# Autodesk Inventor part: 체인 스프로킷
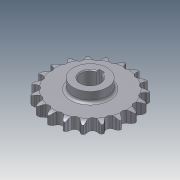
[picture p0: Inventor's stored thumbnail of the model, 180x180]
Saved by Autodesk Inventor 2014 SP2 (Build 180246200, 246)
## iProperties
Created: 2013-01
Part Number: 체인 스프로킷
Material: 강
Document SubType Name: Modeling
Designer: KYOUNG IL JANG
Density: 1 g/cm^3
Appearance: 강철
CustomPartVersion: 1
Company: 한국ATC센터
Author: KYOUNG IL JANG
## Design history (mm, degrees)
sketch "이론적 톱니 프로파일"
  geometry: L1 (0, 0)-(0, 45.567); L2 (0, 0)-(14.795, 43.098); L3 (0, 45.567)-(14.795, 43.098); L4 (0, 45.567)-(5.661, 50.015); L5 (5.661, 50.015)-(-5.141, 45.406); L6 (-12.428, 43.493)-(-5.573, 46.417); L7 (-5.141, 45.406)-(-5.573, 46.417); L8 (5.573, 46.417)-(5.141, 45.406); L9 (0, 0)-(8.138, 48.771); A1 r 45.567 centre (0, 0) between (0, 45.567) and (14.795, 43.098); A2 r 49.445 centre (0, 0) between (7.302, 48.903) and (-7.302, 48.903); A3 r 4.545 centre (0, 45.567) between (-3.574, 42.758) and (3.574, 42.758); A4 r 7.453 centre (12.428, 43.493) between (7.302, 48.903) and (5.573, 46.417); A5 r 7.453 centre (-12.428, 43.493) between (-5.573, 46.417) and (-7.302, 48.903); A6 r 11.745 centre (5.661, 50.015) between (-5.141, 45.406) and (-3.574, 42.758); A7 r 11.745 centre (-5.661, 50.015) between (3.574, 42.758) and (5.141, 45.406); 2 further points
  constraints: 18 end point, 15 point on circle, 7 centre point, 3 coincident, 3 point on line, 3 symmetric about line, 3 tangent, 1 equal radius, 1 midpoint, 1 parallel, 1 vertical, 1 other
  dimensions: "d0" = 91.13301 diameter of A1 (computed from da_p, da_z); "d2" = 18.9474 deg angle of L2 L1 (computed from da_z); "d3" = 4.545 radius of A3 (= 0.5 x da_Dr + da_SC); "d10" = 128.158 deg angle of L4 L1 (computed from da_z); "d11" = 15.0526 deg angle of L5 L4 (computed from da_z); "d12" = 7.2 distance of L3.start L4.end (= 0.8 x da_Dr); "d13" = 11.745 distance of L4.end L5.end (= 1.3 x da_Dr + da_SC); "d14" = 12.6 distance of A4.centre L1.end (= 1.4 x da_Dr); "d23" = 4.5 distance from line of L9.end L3 (= da_Ha)
sketch "톱니 프로파일"
  geometry: L1 (0, 0)-(0, 45.567); L2 (0, 45.567)-(4.203, 43.837); L3 (0, 45.567)-(-4.203, 43.837); A1 r 4.545 centre (0, 45.567) between (-4.203, 43.837) and (4.203, 43.837); A2 r 22.68 centre (25.176, 35.206) between (7.12, 48.93) and (4.203, 43.837); A3 r 22.68 centre (-25.176, 35.206) between (-4.203, 43.837) and (-7.12, 48.93); A4 r 49.445 centre (0, 0) between (-7.12, 48.93) and (7.12, 48.93) reference; 1 further point
  constraints: 9 point on circle, 6 end point, 3 centre point, 2 tangent, 1 coincident, 1 equal radius, 1 vertical, 1 other
  dimensions: "d44" = 135.263 deg angle of L3 L2 (= da_Alfa); "d45" = 22.68 radius of A2 (= da_Re); "d46" = 4.545 radius of A1 (= da_Ri)
sketch "단면 프로파일"
  geometry: L1 (49.445, 0)-(-49.445, 0) reference; L2 (33.265, 6.65)-(-33.265, 6.65); L3 (-33.265, 6.65)-(-33.265, -6.65); L4 (-33.265, -6.65)-(33.265, -6.65); L5 (33.265, -6.65)-(33.265, 6.65); L6 (33.265, 6.65)-(49.445, 6.65); L7 (49.445, 6.65)-(49.445, -6.65); L8 (49.445, -6.65)-(33.265, -6.65); L9 (33.265, -6.65)-(33.265, 6.65); L10 (42.183, 6.65)-(0, 6.65); L11 (0, 6.65)-(0, -6.65); L12 (0, -6.65)-(42.183, -6.65); L13 (0, 6.65)-(0, -6.65); L14 (49.445, 4.775)-(49.445, -4.775); A1 r 15 centre (42.183, -8.35) between (49.445, 4.775) and (42.183, 6.65); A2 r 15 centre (42.183, 8.35) between (42.183, -6.65) and (49.445, -4.775); 2 further points
  constraints: 26 end point, 7 midpoint, 5 perpendicular, 4 parallel, 4 point on circle, 3 point on line, 3 symmetric about line, 2 centre point, 2 horizontal, 2 tangent, 1 collinear, 1 other
  dimensions: "d30" = 13.3 distance between parallel lines of L8 L6 (= da_Bf); "d31" = 66.53007 distance between parallel lines of L3 L5 (= da_Ds); "d32" = 13.3 distance between parallel lines of L4 L2 (= da_Bs); "d33" = 1.875 distance from line of L14.start L6 (= da_Ba); "d34" = 15 radius of A1 (= da_Rx); "d43" = 6.65 distance between parallel lines of L4 L1 (computed from da_k, da_pt, da_Bs)
revolve "슈라우드" stored, may be unused: angle "d36" = 90 deg
revolve "스트랜드" stored, may be unused: angle "d37" = 90 deg
extrude "이론적 톱니" cut sketch "이론적 톱니 프로파일" stored distance "d18" = 10; taper "d19" = 0 deg; dims "d49" = 0, "form_type" = 0 [user parameter]
extrude "톱니" cut sketch "톱니 프로파일" stored distance "d47" = 10; taper "d48" = 0 deg; dims "d50" = 10, "form_type" = 0 [user parameter]
node "타이밍 평면"
node "작업 평면3"
sketch "스케치5"
  geometry: C1 r 20 at (0, -45.567); 1 further point
  constraints: 1 centre point, 1 coincident
  dimensions: "d52" = 40 diameter of C1
extrude "돌출4" join sketch "스케치5" stored distance "d53" = 10; taper "d54" = 0 deg
sketch "스케치6"
  geometry: L1 (3, 10.583)-(3, 13.8); L2 (3, 13.8)-(-3, 13.8); L3 (-3, 13.8)-(-3, 10.583); A1 r 11 centre (0, 0) between (3, 10.583) and (-3, 10.583); 1 further point
  constraints: 6 end point, 2 parallel, 2 point on circle, 1 centre point, 1 coincident, 1 perpendicular, 1 vertical
  dimensions: "d55" = 22 diameter of A1; "d56" = 24.8 dimension on A1 L2 (computed from d55); "d57" = 6 distance of L1.end L2.end
extrude "돌출5" cut sketch "스케치6" stored distance "d58" = 10; taper "d59" = 0 deg
fillet "모깎기2" dims "d60" = 3
chamfer "모따기1" distance "d61" = 1; stored, may be unused: second distance "d62" = 2, angle "d63" = 45 deg
body "Solid1"
pattern_linear "스트랜드 패턴" dims "d40" = 24 (= da_pt)
pattern_circular "톱니 패턴" dims angle "d21" = 360 deg
other parameters: "da_p" = 15 [user parameter; used in 1 equation term], "da_Dr" = 9 [user parameter; used in 4 equation terms], "da_SC" = 0.045 [user parameter; used in 2 equation terms], "da_Ha" = 4.5 [user parameter; used in 1 equation term], "da_pt" = 24 [user parameter; used in 2 equation terms], "da_Bf" = 13.3 [user parameter; used in 1 equation term], "d28" = 0, "d29" = 0, "da_Ba" = 1.875 [user parameter; used in 1 equation term], "da_Rx" = 15 [user parameter; used in 1 equation term], "da_Ra" = 0.6 [user parameter], "da_Bs" = 13.3 [user parameter; used in 2 equation terms], "da_Ds" = 66.53007 [user parameter; used in 1 equation term], "d42" = 0, "da_Re" = 22.68 [user parameter; used in 1 equation term], "da_Ri" = 4.545 [user parameter; used in 1 equation term], "da_Alfa" = 135.263 deg [user parameter; used in 1 equation term], "d51" = -25
